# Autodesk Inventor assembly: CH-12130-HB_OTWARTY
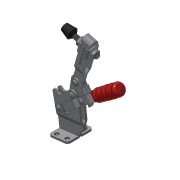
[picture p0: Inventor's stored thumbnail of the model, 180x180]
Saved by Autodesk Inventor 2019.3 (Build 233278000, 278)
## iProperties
Company: Î¢ÈíÖÐ¹ú
Created: 2012-09
Part Number: CH-12130-HB_OTWARTY
Material: Ogólny
Description: STEP AP203
Document SubType Name: Assembly
Designer: CADENGINEERING4
Sending System: SolidWorks 2010
Preprocessor: SwSTEP 2.0
Title: CH-12130-HB.STEP
Author: Î¢ÈíÓÃ»§
Revision Number: ÈÎºÎ
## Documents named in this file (12)
- D:\Vault_2016\Projekty\NASZ KATALOG\CLAMPTEK\STRONA\Vertical toggle clamp\CH-12130-HB\CH-12130-HB_OTWARTY.iam
- D:\Vault_2016\Projekty\NASZ KATALOG\CLAMPTEK\STEP FILES\Vertical toggle clamp\CH-12130-HB\CH-12130-HB-02 U-BAR.ipt
- D:\Vault_2016\Projekty\NASZ KATALOG\CLAMPTEK\STEP FILES\Vertical toggle clamp\CH-12130-HB\CH-12130-03 STRAIGHT HANDLE.ipt
- D:\Vault_2016\Projekty\NASZ KATALOG\CLAMPTEK\STEP FILES\Vertical toggle clamp\CH-12130-HB\CH-12130-07.ipt
- D:\Vault_2016\Projekty\NASZ KATALOG\CLAMPTEK\STEP FILES\Vertical toggle clamp\CH-12130-HB\CH-FC-56212 SPINDLE SUPPLIED.ipt
- D:\Vault_2016\Projekty\NASZ KATALOG\CLAMPTEK\STEP FILES\Vertical toggle clamp\CH-12130-HB\CH-12130-HB-01 FLANGED BASE.ipt
- D:\Vault_2016\Projekty\NASZ KATALOG\CLAMPTEK\STEP FILES\Vertical toggle clamp\CH-12130-HB\CH-12130-05.ipt
- D:\Vault_2016\Projekty\NASZ KATALOG\CLAMPTEK\STEP FILES\Vertical toggle clamp\CH-12130-HB\CH-FC-56212 Nut.ipt
- D:\Vault_2016\Projekty\NASZ KATALOG\CLAMPTEK\STEP FILES\Vertical toggle clamp\CH-12130-HB\CH-12130-08.ipt
- D:\Vault_2016\Projekty\NASZ KATALOG\CLAMPTEK\STEP FILES\Vertical toggle clamp\CH-12130-HB\CH-12130-06.ipt
- D:\Vault_2016\Projekty\NASZ KATALOG\CLAMPTEK\STEP FILES\Vertical toggle clamp\CH-12130-HB\CH-12130-04 CONNECTING-PLATE.ipt
- D:\Vault_2016\Projekty\NASZ KATALOG\CLAMPTEK\STEP FILES\Vertical toggle clamp\CH-12130-HB\CH-FW-516.ipt
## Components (15 placed, 11 different names)
1. CH-12130-HB-01 FLANGED BASE_5
2. CH-12130-HB-02 U-BAR:2 — Zestawiające:6, Zestawiające:9, Zestawiające:23, Zestawiające:24, Kątowe:1, Zestawiające:27, Zestawiające:28, Zestawiające:29, Równoległe:3
3. CH-12130-03 STRAIGHT HANDLE:2 — Zestawiające:2, Zestawiające:3, Zestawiające:4, Zestawiające:12, Zestawiające:14, Zestawiające:15, Zestawiające:16, Zestawiające:17, Zestawiające:18, Zestawiające:30
4. CH-12130-07:2 — Zestawiające:16, Zestawiające:17, Zestawiające:18
5. CH-FC-56212 SPINDLE SUPPLIED:2 — Zestawiające:19, Równoległe:3
6. CH-12130-05:2 — Zestawiające:1
7. CH-FC-56212 Nut:3 — Zestawiające:21, Zestawiające:22, Zestawiające:25, Zestawiające:27, Zestawiające:28
8. CH-12130-08:3 — Zestawiające:1, Zestawiające:2, Zestawiające:3, Zestawiające:4
9. CH-12130-06:3 — Zestawiające:5, Zestawiające:6, Zestawiające:7, Zestawiające:8
10. CH-12130-04 CONNECTING-PLATE:2 — Zestawiające:5, Zestawiające:7, Zestawiające:8, Zestawiające:10, Zestawiające:11, Zestawiające:13, Zestawiające:29, Zestawiające:30
11. CH-12130-06:4 — Zestawiające:9, Zestawiające:10
12. CH-12130-08:4 — Zestawiające:11, Zestawiające:12, Zestawiające:13, Zestawiające:14, Zestawiające:15
13. CH-FW-516:3 — Zestawiające:22, Zestawiające:23, Zestawiające:25, Równoległe:1, Kątowe:1
14. CH-FW-516:4 — Zestawiające:20, Zestawiające:24, Zestawiające:26, Równoległe:1
15. CH-FC-56212 Nut:4 — Zestawiające:19, Zestawiające:20, Zestawiające:21, Zestawiające:26
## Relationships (33: Mate 30, Flush 2, Angle 1)
- Zestawiające:1 [Mate]: CH-12130-05:2 ↔ CH-12130-08:3
- Zestawiające:2 [Mate]: CH-12130-03 STRAIGHT HANDLE:2 ↔ CH-12130-08:3
- Zestawiające:3 [Mate]: CH-12130-03 STRAIGHT HANDLE:2 ↔ CH-12130-08:3
- Zestawiające:4 [Mate]: CH-12130-03 STRAIGHT HANDLE:2 ↔ CH-12130-08:3
- Zestawiające:5 [Mate]: CH-12130-06:3 ↔ CH-12130-04 CONNECTING-PLATE:2
- Zestawiające:6 [Mate]: CH-12130-HB-02 U-BAR:2 ↔ CH-12130-06:3
- Zestawiające:7 [Mate]: CH-12130-06:3 ↔ CH-12130-04 CONNECTING-PLATE:2
- Zestawiające:8 [Mate]: CH-12130-06:3 ↔ CH-12130-04 CONNECTING-PLATE:2
- Zestawiające:9 [Mate]: CH-12130-HB-02 U-BAR:2 ↔ CH-12130-06:4
- Zestawiające:10 [Mate]: CH-12130-04 CONNECTING-PLATE:2 ↔ CH-12130-06:4
- Zestawiające:11 [Mate]: CH-12130-04 CONNECTING-PLATE:2 ↔ CH-12130-08:4
- Zestawiające:12 [Mate]: CH-12130-03 STRAIGHT HANDLE:2 ↔ CH-12130-08:4
- Zestawiające:13 [Mate]: CH-12130-04 CONNECTING-PLATE:2 ↔ CH-12130-08:4
- Zestawiające:14 [Mate]: CH-12130-03 STRAIGHT HANDLE:2 ↔ CH-12130-08:4
- Zestawiające:15 [Mate]: CH-12130-03 STRAIGHT HANDLE:2 ↔ CH-12130-08:4
- Zestawiające:16 [Mate]: CH-12130-03 STRAIGHT HANDLE:2 ↔ CH-12130-07:2
- Zestawiające:17 [Mate]: CH-12130-03 STRAIGHT HANDLE:2 ↔ CH-12130-07:2
- Zestawiające:18 [Mate]: CH-12130-03 STRAIGHT HANDLE:2 ↔ CH-12130-07:2
- Zestawiające:19 [Mate]: CH-FC-56212 SPINDLE SUPPLIED:2 ↔ CH-FC-56212 Nut:4
- Zestawiające:20 [Mate]: CH-FW-516:4 ↔ CH-FC-56212 Nut:4
- Zestawiające:21 [Mate]: CH-FC-56212 Nut:3 ↔ CH-FC-56212 Nut:4
- Zestawiające:22 [Mate]: CH-FC-56212 Nut:3 ↔ CH-FW-516:3
- Zestawiające:23 [Mate]: CH-12130-HB-02 U-BAR:2 ↔ CH-FW-516:3
- Zestawiające:24 [Mate]: CH-12130-HB-02 U-BAR:2 ↔ CH-FW-516:4
- Zestawiające:25 [Mate]: CH-FC-56212 Nut:3 ↔ CH-FW-516:3
- Zestawiające:26 [Mate]: CH-FW-516:4 ↔ CH-FC-56212 Nut:4
- Równoległe:1 [Flush]: CH-FW-516:3 ↔ CH-FW-516:4
- Kątowe:1 [Angle]: CH-12130-HB-02 U-BAR:2 ↔ CH-FW-516:3
- Zestawiające:27 [Mate]: CH-12130-HB-02 U-BAR:2 ↔ CH-FC-56212 Nut:3
- Zestawiające:28 [Mate]: CH-12130-HB-02 U-BAR:2 ↔ CH-FC-56212 Nut:3
- Zestawiające:29 [Mate]: CH-12130-HB-02 U-BAR:2 ↔ CH-12130-04 CONNECTING-PLATE:2
- Zestawiające:30 [Mate]: CH-12130-03 STRAIGHT HANDLE:2 ↔ CH-12130-04 CONNECTING-PLATE:2
- Równoległe:3 [Flush]: CH-12130-HB-02 U-BAR:2 ↔ CH-FC-56212 SPINDLE SUPPLIED:2
